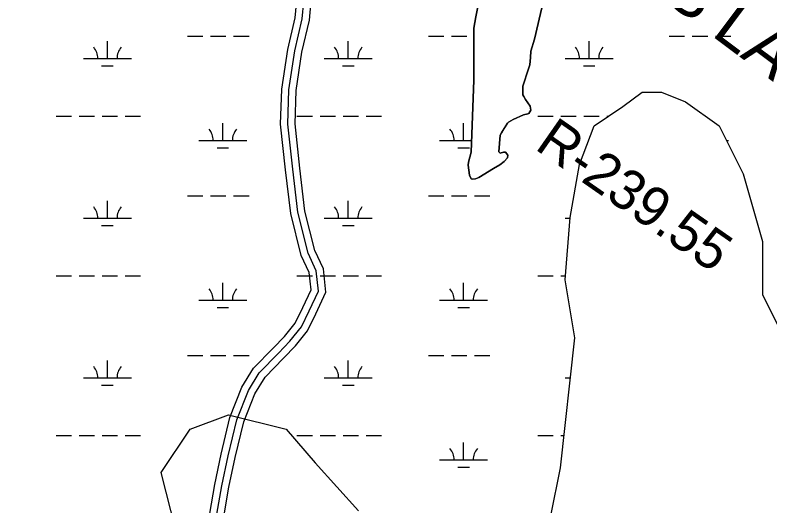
# Model space of a CAD drawing. Extents: x 3281947 to 3319794, y 715894 to 741249.
# Drawn here: x 3293048 to 3294621, y 733724 to 734746 of the extents above; entities that cross this region are included whole.
import ezdxf

# ---------------------------------------------------------------- set-up
doc = ezdxf.new("R2010")
doc.units = 0
for name, color, linetype in [('V-BORW-LINE', 7, 'Continuous'), ('V-RIVR-RANG-IDEN', 7, 'Continuous'), ('V-ROAD-CNTR', 7, 'Continuous'), ('V-SITE-VEGE', 7, 'Continuous'), ('V-TOPO-GNAM-IDEN', 7, 'Continuous'), ('V-TOPO-SHOR', 7, 'Continuous'), ('V-WETL-SWMP', 7, 'Continuous')]:
    doc.layers.add(name, color=color, linetype=linetype)

msp = doc.modelspace()

# ---------------------------------------------------------------- linework, layer by layer
at = {"layer": 'V-BORW-LINE'}
msp.add_spline([(3293535.9, 730584.4), (3293535.4, 730585.3), (3293497, 730657.8), (3293473.2, 730709), (3293458.5, 730751), (3293474.3, 730774.9), (3293498.1, 730803.8), (3293503.4, 730822.7), (3293477.8, 730865.6), (3293442, 730902.7), (3293433.9, 730945), (3293411.4, 730975.9), (3293373.6, 730999.6), (3293329.4, 731009.5), (3293303.1, 731048.1), (3293262.2, 731107.9), (3293205.3, 731214.8), (3293152.6, 731305), (3293107.1, 731394.1), (3293067.5, 731500.7), (3293026.1, 731639), (3292993.6, 731735.4), (3292952.7, 731872.8), (3292925.4, 731981.1), (3292877.6, 732144.9), (3292823.1, 732324.3), (3292751.1, 732547.8), (3292686.3, 732753.5), (3292626.9, 732959.9), (3292578, 733149.6), (3292517.3, 733327.2), (3292468.2, 733513.4), (3292419.2, 733671.8), (3292416, 733774.3), (3292443.1, 733955.9), (3292470.5, 734116.1), (3292505.3, 734342.4), (3292539, 734502.7), (3292585.4, 734750.4), (3292605.6, 734909.3), (3292653.5, 735109.1), (3292667, 735197.9), (3292695.9, 735272.4), (3292816.4, 735423.9), (3292992.8, 735589.4), (3293118.5, 735717.8), (3293151.4, 735720.6), (3293212.8, 735688.5), (3293267.6, 735628.9), (3293299.6, 735578.7), (3293301.8, 735551.8), (3293258, 735404.8), (3293178.9, 735247.8), (3293118.6, 735154.6), (3293020.3, 735075.8), (3292963, 735023.3), (3292899.5, 734947.4), (3292877.5, 734825.5), (3292893.6, 734715.3), (3292909.1, 734596.9), (3292894.2, 734486.7), (3292877, 734359.2), (3292869.2, 734210.8), (3292882, 734024.1), (3292899.4, 733885.4), (3292922.7, 733752.5), (3292923.7, 733661.1), (3292932, 733561), (3292981.6, 733412.2), (3293062.5, 733212.5), (3293111.5, 733047.6), (3293198.7, 732785.6), (3293276, 732606.5), (3293315.6, 732497), (3293336.7, 732448.1), (3293389.1, 732447.8), (3293396.1, 732434.3), (3293380.9, 732420.2), (3293299, 732384.1), (3293266.7, 732364.9), (3293242, 732348.4), (3293249.1, 732332.4), (3293352.9, 732375.1), (3293457.9, 732401.3), (3293485.1, 732328.5), (3293556.5, 732096.9), (3293588.1, 731935.2), (3293608.4, 731793.7), (3293628.6, 731696.8), (3293641.6, 731601.6), (3293698.6, 731490.3), (3293768.8, 731439), (3293849.4, 731356), (3293937.4, 731250.3), (3293976, 731184.6), (3294065.4, 731012.3)], degree=3, dxfattribs=at)
at = {"layer": 'V-ROAD-CNTR'}
for points in [[(3293453.2, 733708.2), (3293463.8, 733768.2), (3293477, 733831.2), (3293495.4, 733907.8), (3293520.2, 733970.8), (3293544.8, 734010.6), (3293585.7, 734052.1), (3293609.2, 734077), (3293631.6, 734104.6), (3293647, 734136.8), (3293664.4, 734174), (3293660.7, 734209.7), (3293643.9, 734245.5), (3293622, 734332.7), (3293611.3, 734423.9), (3293601, 734518.8), (3293603.3, 734592), (3293615.9, 734674.8), (3293631.3, 734740.6), (3293638.1, 734813.9)], [(3293468.1, 733706.6), (3293478.5, 733765.3), (3293491.6, 733827.9), (3293509.7, 733903.3), (3293533.7, 733964.1), (3293556.6, 734001.2), (3293596.5, 734041.7), (3293620.5, 734067.1), (3293644.3, 734096.6), (3293660.6, 734130.4), (3293679.7, 734171.4), (3293675.3, 734213.7), (3293658.1, 734250.6), (3293636.7, 734335.4), (3293626.2, 734425.5), (3293616.1, 734519.3), (3293618.3, 734590.6), (3293630.6, 734672), (3293646.1, 734738.1), (3293652.9, 734811.3)], [(3293483, 733704.9), (3293493.3, 733762.5), (3293506.3, 733824.6), (3293524.1, 733898.8), (3293547.2, 733957.3), (3293568.5, 733991.9), (3293607.3, 734031.2), (3293631.8, 734057.2), (3293657.1, 734088.5), (3293674.1, 734124), (3293695.1, 734168.8), (3293690, 734217.8), (3293672.3, 734255.6), (3293651.5, 734338.1), (3293641.1, 734427.2), (3293631.1, 734519.9), (3293633.3, 734589.3), (3293645.3, 734669.2), (3293661, 734735.7), (3293667.7, 734808.7)]]:
    msp.add_lwpolyline(points, dxfattribs=at)
at = {"layer": 'V-SITE-VEGE'}
msp.add_lwpolyline([(3294011.7, 734763.4), (3294007.6, 734742.6), (3294003.4, 734719.2), (3294003.5, 734610.5), (3293997.8, 734461), (3293992.4, 734439.8), (3293992, 734433.4), (3293994.7, 734413), (3293998.1, 734405), (3293999.8, 734404.1), (3294007, 734405), (3294013.8, 734408), (3294044.7, 734426.4), (3294057.8, 734434.1), (3294067.1, 734441), (3294073.9, 734448.6), (3294074.7, 734454.2), (3294069.6, 734460.9), (3294065.4, 734460.9), (3294058.6, 734458.8), (3294055.6, 734461.7), (3294058.8, 734496.1), (3294061.4, 734500.8), (3294073.6, 734521.3), (3294075.7, 734523), (3294085.4, 734528.9), (3294107, 734538.4), (3294115.9, 734540.6), (3294118.5, 734541.4), (3294122.7, 734548.2), (3294121, 734556.7), (3294111.6, 734570.3), (3294108.1, 734576.6), (3294105.6, 734580.4), (3294105.9, 734598.3), (3294117.2, 734634.4), (3294120.1, 734642.9), (3294121.4, 734657.8), (3294122.6, 734670.9), (3294130.1, 734696), (3294180.1, 734910.3)], dxfattribs=at)
at = {"layer": 'V-TOPO-SHOR'}
msp.add_lwpolyline([(3294180.1, 734910.3), (3294130.1, 734696), (3294122.6, 734670.9), (3294121.4, 734657.8), (3294120.1, 734642.9), (3294117.2, 734634.4), (3294105.9, 734598.3), (3294105.6, 734580.4), (3294108.1, 734576.6), (3294111.6, 734570.3), (3294116.3, 734563.5), (3294121, 734556.7), (3294122.7, 734548.2), (3294118.5, 734541.4), (3294115.9, 734540.6), (3294107, 734538.4), (3294085.4, 734528.9), (3294075.7, 734523), (3294073.6, 734521.3), (3294066.4, 734509.3), (3294061.4, 734500.8), (3294058.8, 734496.1), (3294055.6, 734461.7), (3294058.6, 734458.8), (3294065.4, 734460.9), (3294069.6, 734460.9), (3294074.7, 734454.2), (3294073.9, 734448.6), (3294067.1, 734441), (3294057.8, 734434.1), (3294044.7, 734426.4), (3294013.8, 734408), (3294007, 734405), (3293999.8, 734404.1), (3293998.1, 734405), (3293994.7, 734413), (3293992, 734433.4), (3293992.4, 734439.8), (3293997.8, 734461), (3294003.5, 734610.5), (3294003.4, 734719.2), (3294007.6, 734742.6), (3294011.7, 734763.4)], dxfattribs=at)
at = {"layer": 'V-WETL-SWMP'}
for p, q in [((3293240, 734655.9), (3293240, 734691.9)), ((3293407.1, 734702.3), (3293439.1, 734702.3)), ((3293455.1, 734702.3), (3293487.1, 734702.3)), ((3293503.1, 734702.3), (3293535.1, 734702.3)), ((3293741.9, 734655.9), (3293741.9, 734691.9)), ((3293909, 734702.3), (3293941, 734702.3)), ((3293957, 734702.3), (3293989, 734702.3)), ((3294243.8, 734655.9), (3294243.8, 734691.9)), ((3294410.9, 734702.3), (3294442.9, 734702.3)), ((3294458.9, 734702.3), (3294490.9, 734702.3)), ((3294506.9, 734702.3), (3294538.9, 734702.3)), ((3293190, 734655.9), (3293290, 734655.9)), ((3293691.9, 734655.9), (3293791.9, 734655.9)), ((3294193.8, 734655.9), (3294293.8, 734655.9)), ((3293228, 734640.5), (3293252, 734640.5)), ((3293729.9, 734640.5), (3293753.9, 734640.5)), ((3294231.8, 734640.5), (3294255.8, 734640.5)), ((3293133.2, 734535.8), (3293165.2, 734535.8)), ((3293181.2, 734535.8), (3293213.2, 734535.8)), ((3293229.2, 734535.8), (3293261.2, 734535.8)), ((3293277.2, 734535.8), (3293309.2, 734535.8)), ((3293635.1, 734535.8), (3293667.1, 734535.8)), ((3293683.1, 734535.8), (3293715.1, 734535.8)), ((3293731.1, 734535.8), (3293763.1, 734535.8)), ((3293779.1, 734535.8), (3293811.1, 734535.8)), ((3294137, 734535.8), (3294169, 734535.8)), ((3294185, 734535.8), (3294217, 734535.8)), ((3294233, 734535.8), (3294265, 734535.8)), ((3294281, 734535.8), (3294284.7, 734535.8)), ((3293480.5, 734485.1), (3293480.5, 734521.1)), ((3293982.4, 734485.1), (3293982.4, 734521.1)), ((3293430.5, 734485.1), (3293530.5, 734485.1)), ((3293932.4, 734485.1), (3293998.8, 734485.1)), ((3294529.9, 734485.1), (3294534.3, 734485.1)), ((3293468.5, 734469.7), (3293492.5, 734469.7)), ((3293970.4, 734469.7), (3293994.4, 734469.7)), ((3293240, 734323.2), (3293240, 734359.2)), ((3293407.1, 734369.7), (3293439.1, 734369.7)), ((3293455.1, 734369.7), (3293487.1, 734369.7)), ((3293503.1, 734369.7), (3293535.1, 734369.7)), ((3293741.9, 734323.2), (3293741.9, 734359.2)), ((3293909, 734369.7), (3293941, 734369.7)), ((3293957, 734369.7), (3293989, 734369.7)), ((3294005, 734369.7), (3294037, 734369.7)), ((3293190, 734323.2), (3293290, 734323.2)), ((3293691.9, 734323.2), (3293791.9, 734323.2)), ((3294193.8, 734323.2), (3294203.9, 734323.2)), ((3293228, 734307.8), (3293252, 734307.8)), ((3293729.9, 734307.8), (3293753.9, 734307.8)), ((3293133.2, 734203.2), (3293165.2, 734203.2)), ((3293181.2, 734203.2), (3293213.2, 734203.2)), ((3293229.2, 734203.2), (3293261.2, 734203.2)), ((3293277.2, 734203.2), (3293309.2, 734203.2)), ((3293635.1, 734203.2), (3293667.1, 734203.2)), ((3293683.1, 734203.2), (3293715.1, 734203.2)), ((3293731.1, 734203.2), (3293763.1, 734203.2)), ((3293779.1, 734203.2), (3293811.1, 734203.2)), ((3294137, 734203.2), (3294169, 734203.2)), ((3294185, 734203.2), (3294194.7, 734203.2)), ((3293480.5, 734152.4), (3293480.5, 734188.4)), ((3293982.4, 734152.4), (3293982.4, 734188.4)), ((3293430.5, 734152.4), (3293530.5, 734152.4)), ((3293932.4, 734152.4), (3294032.4, 734152.4)), ((3293468.5, 734137), (3293492.5, 734137)), ((3293970.4, 734137), (3293994.4, 734137)), ((3293407.1, 734037), (3293439.1, 734037)), ((3293455.1, 734037), (3293487.1, 734037)), ((3293503.1, 734037), (3293535.1, 734037)), ((3293909, 734037), (3293941, 734037)), ((3293957, 734037), (3293989, 734037)), ((3294005, 734037), (3294037, 734037)), ((3293240, 733990.6), (3293240, 734026.6)), ((3293741.9, 733990.6), (3293741.9, 734026.6)), ((3293190, 733990.6), (3293290, 733990.6)), ((3293691.9, 733990.6), (3293791.9, 733990.6)), ((3294193.8, 733990.6), (3294204.8, 733990.6)), ((3293228, 733975.1), (3293252, 733975.1)), ((3293729.9, 733975.1), (3293753.9, 733975.1)), ((3293133.2, 733870.5), (3293165.2, 733870.5)), ((3293181.2, 733870.5), (3293213.2, 733870.5)), ((3293229.2, 733870.5), (3293261.2, 733870.5)), ((3293277.2, 733870.5), (3293309.2, 733870.5)), ((3293635.1, 733870.5), (3293667.1, 733870.5)), ((3293683.1, 733870.5), (3293715.1, 733870.5)), ((3293731.1, 733870.5), (3293763.1, 733870.5)), ((3293779.1, 733870.5), (3293811.1, 733870.5)), ((3293982.4, 733819.7), (3293982.4, 733855.7)), ((3294137, 733870.5), (3294169, 733870.5)), ((3294185, 733870.5), (3294191.5, 733870.5)), ((3293932.4, 733819.7), (3294032.4, 733819.7)), ((3293970.4, 733804.3), (3293994.4, 733804.3))]:
    msp.add_line(p, q, dxfattribs=at)
for points in [[(3294011.7, 734763.4), (3294007.6, 734742.6), (3294003.4, 734719.2), (3294003.5, 734610.5), (3293997.8, 734461), (3293992.4, 734439.8), (3293992, 734433.4), (3293994.7, 734413), (3293998.1, 734405), (3293999.8, 734404.1), (3294007, 734405), (3294013.8, 734408), (3294044.7, 734426.4), (3294057.8, 734434.1), (3294067.1, 734441), (3294073.9, 734448.6), (3294074.7, 734454.2), (3294069.6, 734460.9), (3294065.4, 734460.9), (3294058.6, 734458.8), (3294055.6, 734461.7), (3294058.8, 734496.1), (3294061.4, 734500.8), (3294073.6, 734521.3), (3294075.7, 734523), (3294085.4, 734529), (3294107, 734538.4), (3294115.9, 734540.6), (3294118.5, 734541.4), (3294122.7, 734548.2), (3294121, 734556.7), (3294111.6, 734570.3), (3294108.1, 734576.6), (3294105.6, 734580.4), (3294105.9, 734598.3), (3294117.2, 734634.4), (3294120.1, 734642.9), (3294121.4, 734657.8), (3294122.6, 734670.9), (3294130.1, 734696), (3294180.1, 734910.3)], [(3294164, 733703.1), (3294184, 733803.4), (3294214.1, 734074.2), (3294194, 734194.5), (3294204.1, 734324.9), (3294224.1, 734435.2), (3294254.2, 734515.5), (3294314.3, 734555.6), (3294354.4, 734585.7), (3294394.4, 734585.7), (3294444.6, 734565.6), (3294514.7, 734515.5), (3294564.8, 734415.2), (3294604.9, 734274.8), (3294604.9, 734164.5), (3294645, 734084.2)], [(3294819.9, 730595.5), (3294614.9, 731005.5), (3294474.6, 731296.3), (3294354.4, 731617.2), (3294214.1, 731787.7), (3294073.8, 731978.2), (3293562.7, 733201.7), (3293462.5, 733542.7), (3293382.4, 733673.1), (3293352.3, 733793.4), (3293412.4, 733883.7), (3293492.6, 733913.7), (3293612.8, 733883.7), (3293673, 733813.5), (3293763.1, 733713.2)]]:
    msp.add_lwpolyline(points, dxfattribs=at)
for centre, start, end in [((3293184.8, 734656.4), 359.2282, 40.7718), ((3293295.3, 734656.4), 139.2282, 180.7718), ((3293686.7, 734656.4), 359.2282, 40.7718), ((3293797.2, 734656.4), 139.2282, 180.7718), ((3294188.6, 734656.4), 359.2282, 40.7718), ((3294299.1, 734656.4), 139.2282, 180.7718), ((3293425.3, 734485.6), 359.2282, 40.7718), ((3293535.7, 734485.6), 139.2282, 180.7718), ((3293927.2, 734485.6), 359.2282, 40.7718), ((3293184.8, 734323.7), 359.2282, 40.7718), ((3293295.3, 734323.7), 139.2282, 180.7718), ((3293686.7, 734323.7), 359.2282, 40.7718), ((3293797.2, 734323.7), 139.2282, 180.7718), ((3293425.3, 734152.9), 359.2282, 40.7718), ((3293535.7, 734152.9), 139.2282, 180.7718), ((3293927.2, 734152.9), 359.2282, 40.7718), ((3294037.6, 734152.9), 139.2282, 180.7718), ((3293184.8, 733991), 359.2282, 40.7718), ((3293295.3, 733991), 139.2282, 180.7718), ((3293686.7, 733991), 359.2282, 40.7718), ((3293797.2, 733991), 139.2282, 180.7718), ((3293927.2, 733820.2), 359.2282, 40.7718), ((3294037.6, 733820.2), 139.2282, 180.7718)]:
    msp.add_arc(centre, 35.2, start, end, dxfattribs=at)

# ---------------------------------------------------------------- texts
at = {"layer": 'V-RIVR-RANG-IDEN'}
msp.add_text('R-239.55', height=83, rotation=325.1598, dxfattribs=at).set_placement((3294128.3, 734468.4))
at = {"layer": 'V-TOPO-GNAM-IDEN'}
for s, p in [('GROSSMAN OR', (3294197.9, 735122.1)), ('DEVALLS LANDING', (3293985.1, 735088.1))]:
    msp.add_text(s, height=100, rotation=323.1602, dxfattribs=at).set_placement(p)

doc.saveas('drawing.dxf')
